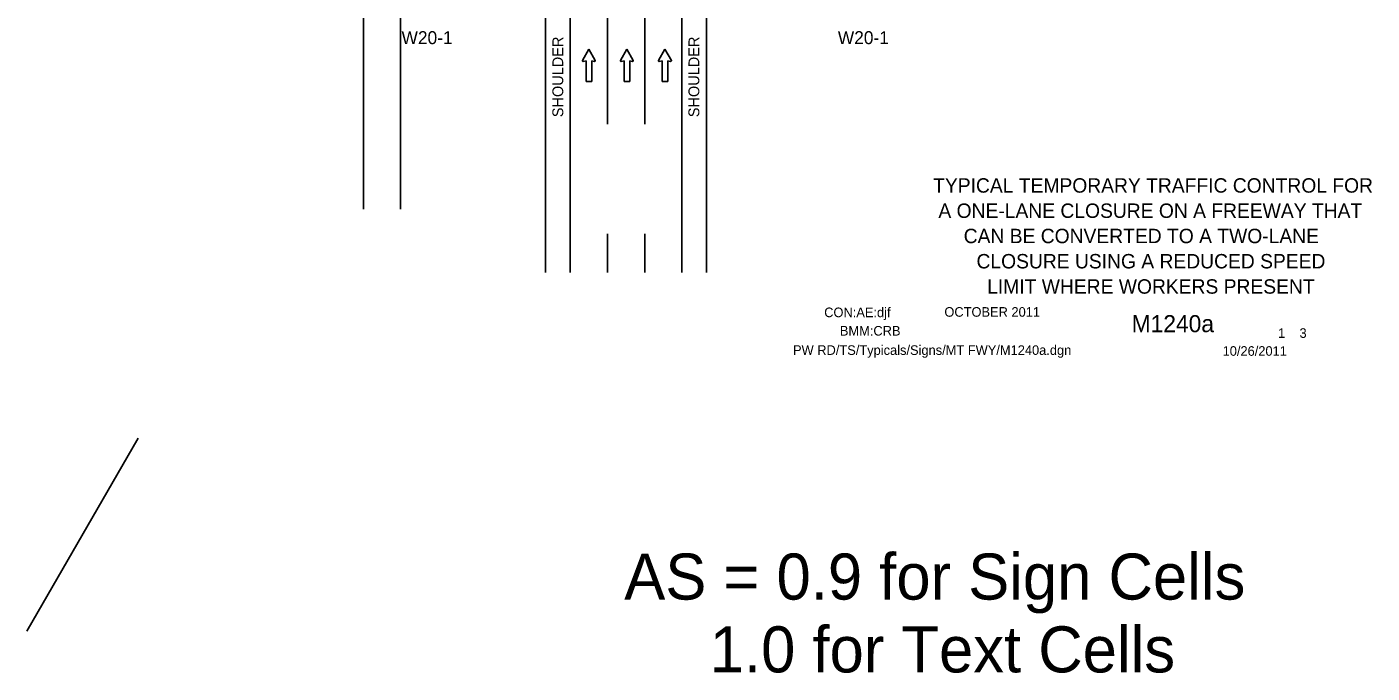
# Model space of a CAD drawing. Extents: x 16576 to 19504, y 5728 to 6974.
# Drawn here: x 16576 to 17444, y 5728 to 6145 of the extents above; entities that cross this region are included whole.
import ezdxf

# ---------------------------------------------------------------- set-up
doc = ezdxf.new("R2010")
doc.units = 0
for name, color, linetype in [('ALI_LEGAL_EX', 7, 'Continuous'), ('BORDER', 7, 'Continuous'), ('BORDER_SIGNAL_WO', 7, 'Continuous'), ('MT_SCRATCH_LEVEL_E', 7, 'Continuous'), ('PAVT_EDGE_EX', 7, 'Continuous'), ('TRAFFIC_SIGNS_PR', 7, 'Continuous'), ('TYPICAL_TEXT_DIMEN_PR', 7, 'Continuous')]:
    doc.layers.add(name, color=color, linetype=linetype)

msp = doc.modelspace()

# ---------------------------------------------------------------- linework, layer by layer
at = {"layer": 'ALI_LEGAL_EX'}
for p, q in [((16950.77, 6911.88), (16950.77, 6082.69)), ((16974.77, 6911.88), (16974.77, 6082.69)), ((16793.2, 6891.57), (16793.2, 6027.66)), ((16817.2, 6891.57), (16817.2, 6027.66))]:
    msp.add_line(p, q, dxfattribs=at)
for points in [[(16950.77, 6086.88), (16950.77, 6111.88)], [(16950.77, 6086.88), (16950.77, 6111.88)], [(16974.77, 6111.88), (16974.77, 6086.88)], [(16950.77, 5986.88), (16950.77, 6011.88)], [(16950.77, 5986.88), (16950.77, 6011.88)], [(16974.77, 6011.88), (16974.77, 5986.88)]]:
    msp.add_lwpolyline(points, dxfattribs=at)
at = {"layer": 'MT_SCRATCH_LEVEL_E'}
for p, q in [((16938.74, 6131.01), (16934.63, 6123.77)), ((16935.11, 6123.08), (16936.89, 6123.4)), ((16936.89, 6123.4), (16936.89, 6110.14)), ((16942.89, 6123.77), (16938.74, 6131.01)), ((16940.63, 6110.14), (16940.63, 6123.4)), ((16940.63, 6123.4), (16942.41, 6123.08)), ((16963.3, 6131.01), (16959.19, 6123.77)), ((16959.67, 6123.08), (16961.45, 6123.4)), ((16961.45, 6123.4), (16961.45, 6110.14)), ((16967.44, 6123.77), (16963.3, 6131.01)), ((16965.19, 6110.14), (16965.19, 6123.4)), ((16965.19, 6123.4), (16966.97, 6123.08)), ((16987.86, 6131.01), (16983.75, 6123.77)), ((16984.23, 6123.08), (16986.01, 6123.4)), ((16986.01, 6123.4), (16986.01, 6110.14)), ((16992, 6123.77), (16987.86, 6131.01)), ((16989.75, 6110.14), (16989.75, 6123.4)), ((16989.75, 6123.4), (16991.53, 6123.08)), ((16936.89, 6110.14), (16940.63, 6110.14)), ((16961.45, 6110.14), (16965.19, 6110.14)), ((16986.01, 6110.14), (16989.75, 6110.14))]:
    msp.add_line(p, q, dxfattribs=at)
for centre, start, end in [((16935.04, 6123.54), 150.42484, 279.96381), ((16942.48, 6123.54), 260.03619, 29.77312), ((16959.59, 6123.54), 150.42484, 279.96381), ((16967.04, 6123.54), 260.03619, 29.77312), ((16984.15, 6123.54), 150.42484, 279.96381), ((16991.59, 6123.54), 260.03619, 29.77312)]:
    msp.add_arc(centre, 0.463, start, end, dxfattribs=at)
at = {"layer": 'PAVT_EDGE_EX'}
for p, q in [((16910.77, 6923.28), (16910.77, 5986.88)), ((16926.77, 6923.28), (16926.77, 5986.88)), ((16998.77, 6923.28), (16998.77, 5986.88)), ((17014.77, 6923.28), (17014.77, 5986.88))]:
    msp.add_line(p, q, dxfattribs=at)
at = {"layer": 'TYPICAL_TEXT_DIMEN_PR'}
msp.add_line((16647.75, 5880), (16575.89, 5755.4), dxfattribs=at)

# ---------------------------------------------------------------- texts
at = {"layer": 'BORDER'}
for s, p in [('TYPICAL TEMPORARY TRAFFIC CONTROL FOR', (17161.04, 6038.42)), ('A ONE-LANE CLOSURE ON A FREEWAY THAT', (17164.42, 6022.12)), ('CAN BE CONVERTED TO A TWO-LANE ', (17180.75, 6005.82)), ('CLOSURE USING A REDUCED SPEED', (17189.02, 5989.52)), ('LIMIT WHERE WORKERS PRESENT', (17195.92, 5973.22))]:
    msp.add_text(s, height=9.3, dxfattribs=at).set_placement(p)
at = {"layer": 'BORDER_SIGNAL_WO'}
for s, height, p in [('CON:AE:djf  ', 6.2, (17090.69, 5958.06)), ('    OCTOBER 2011    ', 6.2, (17159.08, 5958.34)), ('    M1240a   ', 11, (17272.86, 5948.38)), ('BMM:CRB   ', 6.2, (17100.81, 5946.17)), (' 1    3 ', 6.2, (17381.45, 5944.7)), ('PW RD/TS/Typicals/Signs/MT FWY/M1240a.dgn      ', 6.2, (17070.55, 5933.71)), ('10/26/2011    ', 6.2, (17347.93, 5933.13)), ('AS = 0.9 for Sign Cells', 29.7271, (16961.58, 5775.8)), ('     1.0 for Text Cells', 29.7271, (16961.58, 5728.8))]:
    msp.add_text(s, height=height, dxfattribs=at).set_placement(p)
at = {"layer": 'TRAFFIC_SIGNS_PR'}
for p in [(16817.79, 6134.26), (17099.49, 6134.26)]:
    msp.add_text('W20-1', height=8.37, dxfattribs=at).set_placement(p)
at = {"layer": 'TYPICAL_TEXT_DIMEN_PR'}
for p in [(16922.19, 6087.12), (17010.05, 6087.12)]:
    msp.add_text('SHOULDER', height=7, rotation=90, dxfattribs=at).set_placement(p)

doc.saveas('drawing.dxf')
